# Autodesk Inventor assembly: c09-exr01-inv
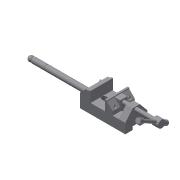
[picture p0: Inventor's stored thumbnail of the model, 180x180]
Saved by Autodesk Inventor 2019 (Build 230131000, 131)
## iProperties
Created: 2011-07
Part Number: c09-exr01-inv
Document SubType Name: Assembly
Designer: CadCim
Author: CadCim
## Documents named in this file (9)
- E:\_Deepak\Inventor\Projects\Autodesk Inventor_2019_Project\Resources\Inventor_2018_tut\c13_Inv_2019_tut\c13_Inv_tut_2019\c13-tut02-inv\Drill Press vice\Drill Press Vice\c09-exr01-inv.iam
- E:\_Deepak\Inventor\Projects\Autodesk Inventor_2019_Project\Resources\Inventor_2018_tut\c13_Inv_2019_tut\c13_Inv_tut_2019\c13-tut02-inv\Drill Press vice\Drill Press Vice\Base.ipt
- E:\_Deepak\Inventor\Projects\Autodesk Inventor_2019_Project\Resources\Inventor_2018_tut\c13_Inv_2019_tut\c13_Inv_tut_2019\c13-tut02-inv\Drill Press vice\Drill Press Vice\Jaw Face.ipt
- E:\_Deepak\Inventor\Projects\Autodesk Inventor_2019_Project\Resources\Inventor_2018_tut\c13_Inv_2019_tut\c13_Inv_tut_2019\c13-tut02-inv\Drill Press vice\Drill Press Vice\Movable Jaw.ipt
- E:\_Deepak\Inventor\Projects\Autodesk Inventor_2019_Project\Resources\Inventor_2018_tut\c13_Inv_2019_tut\c13_Inv_tut_2019\c13-tut02-inv\Drill Press vice\Drill Press Vice\Safety Handle.ipt
- E:\_Deepak\Inventor\Projects\Autodesk Inventor_2019_Project\Resources\Inventor_2018_tut\c13_Inv_2019_tut\c13_Inv_tut_2019\c13-tut02-inv\Drill Press vice\Drill Press Vice\Clamp Screw.ipt
- E:\_Deepak\Inventor\Projects\Autodesk Inventor_2019_Project\Resources\Inventor_2018_tut\c13_Inv_2019_tut\c13_Inv_tut_2019\c13-tut02-inv\Drill Press vice\Drill Press Vice\Clamp Screw Handle.ipt
- E:\_Deepak\Inventor\Projects\Autodesk Inventor_2019_Project\Resources\Inventor_2018_tut\c13_Inv_2019_tut\c13_Inv_tut_2019\c13-tut02-inv\Drill Press vice\Drill Press Vice\Handle Stop.ipt
- E:\_Deepak\Inventor\Projects\Autodesk Inventor_2019_Project\Resources\Inventor_2018_tut\c13_Inv_2019_tut\c13_Inv_tut_2019\c13-tut02-inv\Drill Press vice\Drill Press Vice\Cap Screw.ipt
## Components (13 placed, 8 different names)
1. Base:1 — Insert:3, Insert:9, Insert:10, Mate:8, Mate:9, Mate:12, Mate:13
2. Jaw Face:1 — Mate:10, Mate:11, Mate:12
3. Movable Jaw:1 — Mate:3, Insert:4, Insert:11, Insert:12, Mate:9, Mate:13, Mate:15
4. Safety Handle:1 — Insert:3
5. Clamp Screw:1 — Mate:3, Insert:4, Mate:4, Mate:6, Mate:8
6. Clamp Screw Handle:1 — Mate:4, Insert:7, Insert:8
7. Jaw Face:2 — Mate:14, Mate:15
8. Handle Stop:1 — Insert:7, Mate:6
9. Handle Stop:2 — Insert:8
10. Cap Screw:1 — Insert:12
11. Cap Screw:2 — Insert:11, Mate:14
12. Cap Screw:3 — Insert:10, Mate:11
13. Cap Screw:4 — Insert:9, Mate:10
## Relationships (19: Mate 11, Insert 8)
- Insert:3: Base:1 ↔ Safety Handle:1
- Mate:3: Movable Jaw:1 ↔ Clamp Screw:1
- Insert:4: Movable Jaw:1 ↔ Clamp Screw:1
- Mate:4: Clamp Screw:1 ↔ Clamp Screw Handle:1
- Insert:7: Clamp Screw Handle:1 ↔ Handle Stop:1
- Insert:8: Clamp Screw Handle:1 ↔ Handle Stop:2
- Mate:6: Clamp Screw:1 ↔ Handle Stop:1
- Insert:9: Base:1 ↔ Cap Screw:4
- Insert:10: Base:1 ↔ Cap Screw:3
- Insert:11: Movable Jaw:1 ↔ Cap Screw:2
- Insert:12: Movable Jaw:1 ↔ Cap Screw:1
- Mate:8: Base:1 ↔ Clamp Screw:1
- Mate:9: Base:1 ↔ Movable Jaw:1
- Mate:10: Jaw Face:1 ↔ Cap Screw:4
- Mate:11: Jaw Face:1 ↔ Cap Screw:3
- Mate:12: Base:1 ↔ Jaw Face:1
- Mate:13: Base:1 ↔ Movable Jaw:1
- Mate:14: Jaw Face:2 ↔ Cap Screw:2
- Mate:15: Movable Jaw:1 ↔ Jaw Face:2
